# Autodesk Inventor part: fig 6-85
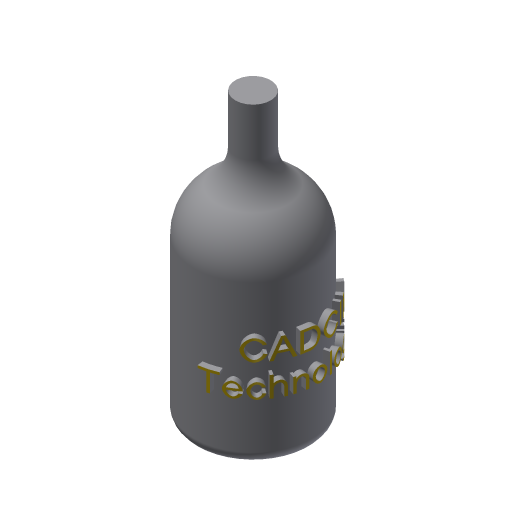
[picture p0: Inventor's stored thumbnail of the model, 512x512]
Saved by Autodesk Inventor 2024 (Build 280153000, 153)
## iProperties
Shininess: 64.0
Length Units: 11269
Angle Units: 11279
Time Units: 11290
Mass Units: 11283
Length Display Precision: 3
Angle Display Precision: 2
Compacted: True
Part Number: fig 6-85
Document SubType Name: Modeling
Created: 2002-12
Designer: deepak
Density: 1 g/cm^3
Material: Generic
Appearance: Default
Density: 0.0
Volumn: 0.0
Area: 0.0
PropertySet Name: Model Information
Control State: 0
Master: False
Checked Out: False
Author: deepak
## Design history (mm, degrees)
sketch "Sketch2"
  geometry: L1 (-7.653, 24.992)-(-7.653, 16.776); L2 (-14.653, 3.659)-(-14.653, -3.57); L3 (-14.653, -3.57)-(-14.653, -23.329); L4 (-14.653, -23.329)-(-4.653, -23.329); L5 (-4.653, -23.329)-(-4.653, 24.992); L6 (-4.653, 24.992)-(-7.653, 24.992); A1 r 6.757 centre (-14.41, 16.776) between (-10.649, 11.163) and (-7.653, 16.776); A2 r 9.033 centre (-5.62, 3.659) between (-10.649, 11.163) and (-14.653, 3.659)
  constraints: 12 end point, 4 point on circle, 3 tangent, 2 centre point, 2 parallel, 2 perpendicular, 1 collinear, 1 vertical
  dimensions: "d0" = 3 distance of L5.end L1.start; "d1" = 10 distance of L3.end L4.end
revolve "Revolution1" sketch "Sketch2" stored, may be unused: angle "d2" = 90 deg
fillet "Fillet1" dims "d3" = 2
workplane "Work Plane1"
workplane "Work Plane2"
sketch "Sketch3"
  geometry: L1 (-24.815, -3.793)-(24.913, -3.793); L2 (24.913, -3.793)-(24.913, -8.382); L3 (24.913, -8.382)-(-24.815, -8.382); L4 (-24.815, -8.382)-(-24.815, -3.793)
  constraints: 2 other
emboss "Emboss1" sketch "Sketch3" dims "d5" = 1, "d6" = 0
body "Solid1"
node "Sketch1"
other parameters: "d4" = 3.5
